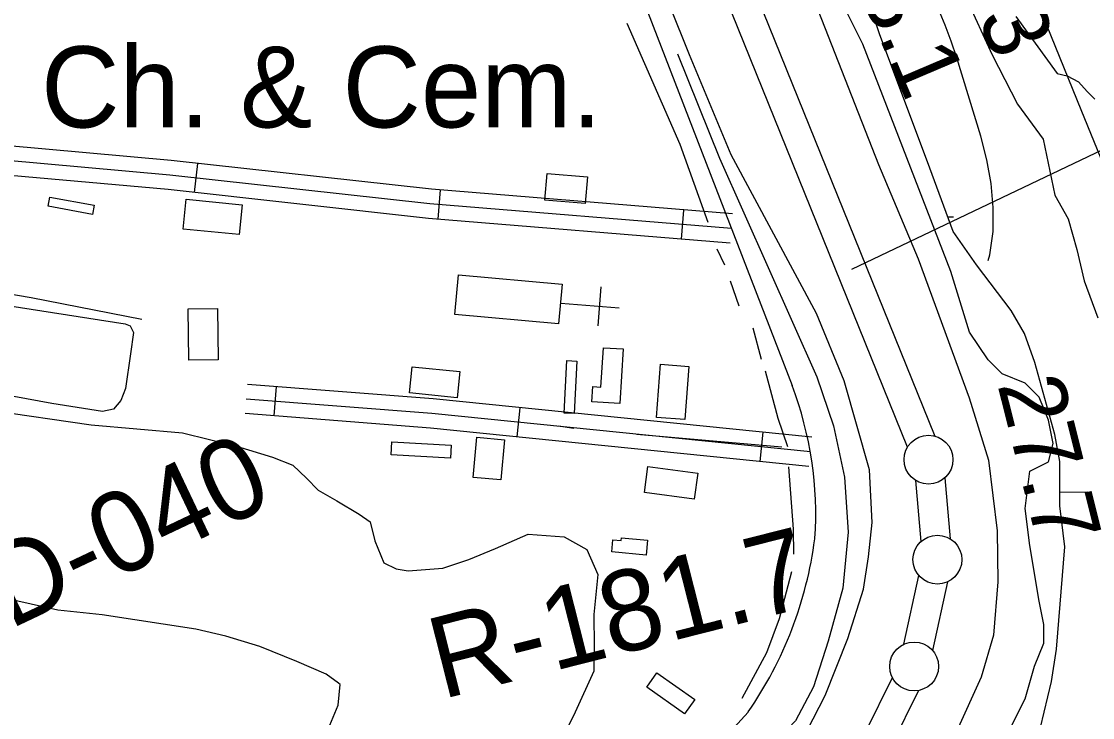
# Model space of a CAD drawing. Extents: x 3355724 to 3393621, y 594744 to 620174.
# Drawn here: x 3383371 to 3384466, y 602796 to 603509 of the extents above; entities that cross this region are included whole.
import ezdxf

# ---------------------------------------------------------------- set-up
doc = ezdxf.new("R2010")
doc.units = 0
for name, color, linetype in [('V-BLDG-OTLN', 7, 'Continuous'), ('V-DTCH-CNTR', 7, 'Continuous'), ('V-LEVE-TOET', 7, 'Continuous'), ('V-RIVR-EDGE', 7, 'Continuous'), ('V-RIVR-RANG', 7, 'Continuous'), ('V-RIVR-RANG-IDEN', 7, 'Continuous'), ('V-ROAD-CNTR', 7, 'Continuous'), ('V-SITE-OTLN', 7, 'Continuous'), ('V-SITE-OTLN-IDEN', 7, 'Continuous'), ('V-SITE-VEGE', 7, 'Continuous'), ('V-SURV-LINE', 7, 'Continuous'), ('V-TOPO-MAJR', 7, 'Continuous'), ('V-TOPO-SHOR', 7, 'Continuous'), ('V-WETL-SWMP', 7, 'Continuous')]:
    doc.layers.add(name, color=color, linetype=linetype)

msp = doc.modelspace()

# ---------------------------------------------------------------- linework, layer by layer
at = {"layer": 'V-BLDG-OTLN'}
for points in [[(3383908.5, 603353.1), (3383949.7, 603349.5), (3383947.3, 603322.2), (3383906.1, 603325.8)], [(3383399.5, 603328.9), (3383445, 603320.4), (3383443.2, 603311), (3383397.8, 603319.5)], [(3383539.1, 603326.6), (3383596.4, 603321), (3383593.4, 603290.5), (3383536.1, 603296)], [(3383817.8, 603249.4), (3383923.9, 603239.6), (3383920.2, 603199.1), (3383814, 603208.8)], [(3383571.3, 603214.7), (3383572, 603162.4), (3383542, 603162), (3383541.3, 603214.3)], [(3383986.2, 603173.5), (3383982.8, 603117.6), (3383954.3, 603119.4), (3383955.3, 603134.8), (3383963.5, 603134.3), (3383966, 603174.7)], [(3383770.2, 603155.2), (3383819.1, 603150.3), (3383816.4, 603123.5), (3383767.5, 603128.4)], [(3383938.9, 603161), (3383936.2, 603107.2), (3383925.8, 603107.8), (3383928.5, 603161.5)], [(3384053.4, 603155.6), (3384049.3, 603101.1), (3384020.4, 603103.3), (3384024.5, 603157.8)], [(3383749.6, 603078.2), (3383810.3, 603074.9), (3383809.6, 603061.7), (3383748.9, 603065)], [(3383864.7, 603080.5), (3383861.1, 603039.3), (3383832.9, 603041.8), (3383836.5, 603083)], [(3384011.6, 603053.1), (3384062.6, 603046.2), (3384058.9, 603019.6), (3384007.9, 603026.6)], [(3383984.6, 602980.2), (3384011.2, 602977.8), (3384009.8, 602962.5), (3383974.6, 602965.7), (3383975.7, 602978), (3383984.3, 602977.2)], [(3384020.7, 602841.9), (3384059.4, 602814.5), (3384049.1, 602799.9), (3384010.4, 602827.3)]]:
    msp.add_lwpolyline(points, close=True, dxfattribs=at)
at = {"layer": 'V-DTCH-CNTR'}
msp.add_lwpolyline([(3383342.9, 603219.8), (3383476.8, 603199.2), (3383481.7, 603197.2), (3383481.7, 603197.2), (3383485.3, 603190.3), (3383482.1, 603168.5), (3383477, 603132.8), (3383472.3, 603120.8), (3383464.7, 603111.6), (3383453.5, 603109.3), (3383401.6, 603117.7), (3383336.4, 603129.5)], dxfattribs=at)
at = {"layer": 'V-LEVE-TOET'}
for points in [[(3383511.6, 605084.7), (3383574.3, 604975.1), (3383627.4, 604850.1), (3383694.6, 604700.2), (3383729.7, 604619.8), (3383745.1, 604594.8), (3383764.1, 604575.9), (3383781.9, 604561.4), (3383793.6, 604547.4), (3383799.7, 604528.5), (3383801.7, 604504.7), (3383798.1, 604491.2), (3383797.6, 604463.1), (3383807.5, 604430.8), (3383892.6, 604235.2), (3383960.5, 604073.6), (3384024, 603920.7), (3384108, 603704.2), (3384171.6, 603555.5), (3384247.5, 603362.3)], [(3384096.6, 603372), (3384054.1, 603474.4), (3384014.5, 603573.2), (3383970.1, 603676.2), (3383930.7, 603768.8), (3383902.2, 603842), (3383860.3, 603941.9), (3383827.6, 604026), (3383786.8, 604124.2), (3383748, 604213.2), (3383707.3, 604311.3), (3383669, 604402.1), (3383631.3, 604501.5), (3383574.6, 604638.6), (3383536.3, 604736.8), (3383486.3, 604853.2), (3383452.4, 604928.1), (3383417.9, 604989.7), (3383371.8, 605068.8)], [(3384247.5, 603362.3), (3384288, 603265.6), (3384340.3, 603123.5), (3384360, 603059.4), (3384368.7, 602987.4), (3384369.4, 602934.9), (3384365.2, 602880.3), (3384352.5, 602837.4), (3384327.4, 602781.8), (3384263.6, 602681.6), (3384175.5, 602576.8), (3384091.9, 602494.5), (3383993, 602404.3), (3383883.1, 602305.6), (3383782.8, 602218.1), (3383685.1, 602142.6), (3383599.3, 602070.8), (3383584.9, 602047.5), (3383541.4, 602002.1)], [(3384151.9, 602746.1), (3384168.3, 602770.8), (3384192.9, 602818.7), (3384215.9, 602877.1), (3384232, 602927.7), (3384237.2, 602960.7), (3384240.9, 602995.8), (3384238.1, 603049.6), (3384212.3, 603140.9), (3384184.1, 603209.8), (3384096.6, 603372)]]:
    msp.add_lwpolyline(points, dxfattribs=at)
at = {"layer": 'V-RIVR-EDGE'}
msp.add_spline([(3382685.2, 606951.8), (3382699.4, 606928.4), (3382711.8, 606916.3), (3382716.9, 606906), (3382724.9, 606891.8), (3382727.4, 606883), (3382735.5, 606874.6), (3382743.1, 606862.5), (3382749.7, 606847.8), (3382757.7, 606833.2), (3382769.7, 606814.2), (3382782.1, 606791.1), (3382790, 606772.8), (3382795.5, 606757.4), (3382803.9, 606738.8), (3382815.9, 606716.1), (3382833, 606684.6), (3382843.1, 606660.1), (3382859.5, 606629.7), (3382875.2, 606604.8), (3382892.7, 606579.2), (3382909.8, 606553.2), (3382929.1, 606522.4), (3382946.9, 606497.2), (3382961.9, 606475.9), (3382973.2, 606466.8), (3382978.6, 606458.7), (3382989.2, 606442.6), (3382998.3, 606426.5), (3383008.1, 606410.7), (3383014.7, 606399.4), (3383025.6, 606390.2), (3383035.5, 606378.9), (3383042.4, 606369.7), (3383049.7, 606356.5), (3383077.3, 606319.5), (3383102.5, 606284), (3383117.1, 606263.2), (3383116.7, 606258), (3383121.8, 606250.7), (3383131.6, 606239), (3383143.6, 606222.1), (3383154.2, 606202.7), (3383171.3, 606174.9), (3383191.3, 606140.5), (3383212.1, 606099.5), (3383234.2, 606053), (3383253.5, 606015), (3383268.8, 605988.3), (3383282.6, 605965.6), (3383296.1, 605942.5), (3383311, 605917.6), (3383331.4, 605885.4), (3383347.5, 605861.2), (3383359.5, 605840), (3383382.8, 605801.5), (3383403.9, 605764.9), (3383419.5, 605733.8), (3383436.6, 605710.8), (3383464.3, 605675.6), (3383488.4, 605644.5), (3383503.7, 605625), (3383518.6, 605606.4), (3383529.6, 605590.3), (3383543.8, 605575.6), (3383545.2, 605570.8), (3383546.7, 605564.6), (3383550.3, 605557.3), (3383562, 605549.6), (3383575.1, 605539.3), (3383595.9, 605513.7), (3383606.8, 605500.9), (3383607.9, 605493.9), (3383610.4, 605479.7), (3383611.9, 605471.2), (3383617, 605461), (3383626.1, 605438.7), (3383628.9, 605416.4), (3383634.4, 605397), (3383636.2, 605387.5), (3383638, 605374.3), (3383643, 605364.1), (3383654.3, 605347.6), (3383664.2, 605328.6), (3383678.7, 605296), (3383684.5, 605268.6), (3383701.5, 605220.3), (3383711.7, 605194.6), (3383715, 605180), (3383724, 605149.3), (3383729.8, 605134.3), (3383736, 605118.6), (3383753.8, 605084.9), (3383770.6, 605064.7), (3383787.4, 605049), (3383790.6, 605036.5), (3383801.2, 605013.1), (3383814.6, 604980.5), (3383827.4, 604948.7), (3383833.5, 604933), (3383843.7, 604917.2), (3383863, 604890.5), (3383884.5, 604857.2), (3383935.1, 604783.6), (3383963.9, 604731.6), (3383993.7, 604668.7), (3384001, 604651.5), (3384017.4, 604619.6), (3384033, 604587), (3384044.7, 604571.3), (3384055.6, 604554.1), (3384071.6, 604521.1), (3384078.5, 604500.3), (3384081.7, 604484.6), (3384087.9, 604472.1), (3384096.7, 604460.8), (3384103.2, 604452.3), (3384105.4, 604442.5), (3384107.2, 604435.9), (3384108.7, 604434.4), (3384114.9, 604433.7), (3384119.6, 604430.7), (3384126.5, 604421.9), (3384146.9, 604390.5), (3384166.9, 604355.7), (3384183.3, 604328.2), (3384207, 604298.9), (3384223.4, 604274), (3384250.3, 604225.3), (3384274, 604180), (3384294, 604141.5), (3384308.5, 604112.6), (3384320.9, 604089.5), (3384332.2, 604075.6), (3384335.8, 604069), (3384345.3, 604053.3), (3384349, 604047.8), (3384362.1, 604035), (3384372.3, 604022.9), (3384383.9, 604005.7), (3384390.1, 603992.9), (3384406.2, 603972.4), (3384417.1, 603955.2), (3384430.6, 603933.9), (3384440.8, 603916.7), (3384450.2, 603895.9), (3384454.2, 603879), (3384458.5, 603863.7), (3384464.3, 603844.6), (3384471.6, 603825.2), (3384474.9, 603815), (3384473.7, 603806.6), (3384477.7, 603791.2), (3384479.2, 603782.1), (3384477.7, 603771.1), (3384476.2, 603762), (3384476.2, 603748.8), (3384482, 603727.6), (3384486.7, 603712.3), (3384487, 603701.3), (3384487, 603678.6), (3384496.3, 603630), (3384507.6, 603590.8), (3384519.5, 603555.7), (3384533.4, 603523.5), (3384552.6, 603483.6), (3384569, 603455.8), (3384585.8, 603432.7), (3384604.3, 603404.5), (3384620.7, 603379.6), (3384633.8, 603347.1), (3384649.1, 603299.9), (3384654.8, 603268.1), (3384673.3, 603196.4), (3384684.5, 603140.8), (3384695.3, 603099.8), (3384709.2, 603067.6), (3384721.9, 603042.4), (3384733.5, 603015.6), (3384746.6, 602984.9), (3384755, 602962.2), (3384756.8, 602956), (3384760.4, 602956), (3384764.4, 602951.2), (3384767.7, 602926.7), (3384780.3, 602867.1), (3384791.2, 602833.8), (3384810.8, 602780.4), (3384833, 602721.9), (3384845.3, 602691.5), (3384855.1, 602674.7), (3384859.5, 602657.8), (3384867.5, 602641.7), (3384876.9, 602624.5), (3384884.6, 602600.7), (3384894, 602572.2), (3384900.5, 602547), (3384906.7, 602528.3), (3384922.7, 602491.3), (3384928.8, 602472.3), (3384931.7, 602454), (3384931.3, 602436.9), (3384923.2, 602425.2), (3384917, 602416.1), (3384910.8, 602406.9), (3384908.2, 602392.3), (3384903, 602383.2), (3384897.5, 602375.9), (3384886.5, 602362), (3384870.4, 602324.1), (3384866.3, 602310.9), (3384859.7, 602289.4), (3384857.5, 602280.2), (3384853.4, 602271.8), (3384850.1, 602256.5), (3384849.3, 602232), (3384850.7, 602216.6), (3384853.2, 602202.4), (3384853.6, 602202.4), (3384862, 602201.2), (3384874.1, 602196.5), (3384877.3, 602195.4), (3384877.3, 602192.4), (3384871.5, 602184), (3384871.1, 602180.4), (3384872.9, 602176.7), (3384876.2, 602170.9), (3384874.7, 602165), (3384869.6, 602153.7), (3384865.5, 602149.3), (3384863, 602143.1), (3384862.9, 602137.6), (3384862.9, 602133.3), (3384868, 602129.6), (3384875.7, 602123), (3384879, 602114.9), (3384881.9, 602107.3), (3384887, 602100.7), (3384894.3, 602097), (3384896.5, 602092.2), (3384897.2, 602079.4), (3384899.7, 602068.1), (3384904.8, 602054.9), (3384914.2, 602039.5), (3384933.2, 602016.8), (3384944.9, 601998.2), (3384955.4, 601973.3), (3384961.9, 601937.8), (3384969.5, 601902), (3384976.3, 601868.7), (3384986.5, 601837.6), (3384990.8, 601821.5), (3384996.2, 601784.6), (3385007.4, 601717.3), (3385010.6, 601690.6), (3385019.6, 601642.3), (3385024.3, 601622.9), (3385033.4, 601587.1), (3385047.9, 601537.3), (3385059.8, 601482.8), (3385064.1, 601458.7), (3385063.7, 601433.8), (3385064.8, 601415.9), (3385066.9, 601389.2), (3385067.9, 601365.1), (3385069, 601353.4), (3385072.6, 601339.9), (3385083.5, 601316.8), (3385087.9, 601310.6), (3385095.6, 601305.1), (3385098.1, 601299.6), (3385101.8, 601293.7), (3385102.5, 601289), (3385102.5, 601285.7), (3385105.8, 601284.6), (3385109.8, 601282.4), (3385109.8, 601280.9), (3385112.7, 601280.5), (3385119.6, 601280.5), (3385121.8, 601278.3), (3385122.2, 601265.2), (3385118.1, 601257.1), (3385117.7, 601251.3), (3385118.1, 601238.1), (3385119.8, 601205.6), (3385118, 601200.8), (3385117.6, 601193.9), (3385120.9, 601189.1), (3385123.1, 601189.1), (3385128.5, 601189.1), (3385132.2, 601189.1), (3385142.8, 601181.8), (3385149, 601173), (3385150.8, 601159.5), (3385150.4, 601141.5), (3385148.5, 601137.5), (3385144.9, 601132.8), (3385144.1, 601125.8), (3385146.3, 601120), (3385150.3, 601115.6), (3385159.8, 601111.2), (3385160.1, 601107.2), (3385154.7, 601103.9), (3385152.8, 601099.1), (3385152.8, 601092.9), (3385153.5, 601084.9), (3385156.8, 601080.1), (3385159.3, 601079.4), (3385173.2, 601082.3), (3385173.2, 601080.8), (3385172.8, 601061.4), (3385176.1, 601037.7), (3385179, 601025.6), (3385187, 601006.9), (3385193.5, 600994.8), (3385203, 600979.8), (3385216.5, 600962.3), (3385223.7, 600948), (3385225.9, 600931.2), (3385225.8, 600905.6), (3385225.4, 600892), (3385233.1, 600875.6), (3385237.4, 600855.5), (3385241.3, 600826.6), (3385242.4, 600796.6), (3385245.5, 600741.4), (3385245.8, 600708.9), (3385249.6, 600639.4), (3385250.3, 600596.6), (3385259.6, 600509.6), (3385266.4, 600451.1), (3385277.5, 600369.2), (3385281.8, 600323.5), (3385282.7, 600271.6), (3385283.4, 600237.2), (3385284.3, 600195.1)], degree=3, dxfattribs=at)
at = {"layer": 'V-RIVR-RANG'}
msp.add_line((3384220, 603255.1), (3385050.3, 603651.4), dxfattribs=at)
at = {"layer": 'V-ROAD-CNTR'}
for p, q in [((3383547.8, 603333.5), (3383551.1, 603363.3)), ((3383796.8, 603306.2), (3383799.2, 603336.1)), ((3384045.9, 603285.7), (3384048.4, 603315.6)), ((3383629, 603104.9), (3383631.4, 603134.8)), ((3383877.7, 603083.4), (3383880.7, 603113.2)), ((3384126.5, 603058.2), (3384129.5, 603088.1))]:
    msp.add_line(p, q, dxfattribs=at)
for points in [[(3382114.2, 606889.5), (3382318.1, 606591.4), (3382554.9, 606233.6), (3382633.5, 606115.6), (3382780.5, 605897.5), (3382958.4, 605622.5), (3383146.4, 605341.9), (3383279.8, 605147.1), (3383351.2, 605037.9), (3383418.1, 604924.1), (3383451.1, 604860.5), (3383485.5, 604784.6), (3383628.2, 604432.8), (3383792.7, 604038.1), (3383916.7, 603743.2), (3383965, 603638.1), (3384159, 603136)], [(3384098.2, 603311.6), (3383790, 603336.9), (3383523.8, 603366.4), (3383307.9, 603385.6), (3383070.5, 603410)], [(3384097, 603296.6), (3383788.5, 603321.9), (3383522.3, 603351.4), (3383306.5, 603370.7), (3383069, 603395.1)], [(3384095.7, 603281.7), (3383787.1, 603307), (3383520.8, 603336.5), (3383305, 603355.8), (3383067.5, 603380.2)], [(3384179.2, 603083.1), (3383791.7, 603122.2), (3383601.8, 603137.1)], [(3384177.7, 603068.1), (3383790.3, 603107.3), (3383600.6, 603122.1)], [(3384176.2, 603053.2), (3383789, 603092.3), (3383599.4, 603107.2)], [(3384114.1, 602801.8), (3383952.3, 602624.5), (3383735.4, 602405.1), (3383594.6, 602283.8), (3383229.2, 601986.7), (3383078.6, 601871.4), (3383013.6, 601825.4), (3382898.3, 601744.6), (3382671.4, 601604.9), (3382435.6, 601459.3), (3382349.1, 601405.5), (3382248.5, 601337.8)]]:
    msp.add_lwpolyline(points, dxfattribs=at)
for centre, radius, start, end in [((3383814.4, 603004.6), 368.8, 356.0617, 20.8662), ((3383784.7, 603030.2), 400.8, 325.2664, 352.6581)]:
    msp.add_arc(centre, radius, start, end, dxfattribs=at)
at = {"layer": 'V-SITE-OTLN'}
for p, q in [((3383960.6, 603197), (3383963.7, 603236.9)), ((3383922.3, 603220.1), (3383982.1, 603215.4))]:
    msp.add_line(p, q, dxfattribs=at)
at = {"layer": 'V-SITE-VEGE'}
for p, q in [((3384231.3, 603485.3), (3384212.3, 603523.4)), ((3384388, 603513.8), (3384430.2, 603455.3)), ((3384321.5, 603252.5), (3384231.3, 603485.3)), ((3384430.2, 603455.3), (3384440.4, 603453)), ((3384440.4, 603453), (3384452.2, 603446.9)), ((3384452.2, 603446.9), (3384460.9, 603436.9)), ((3384460.9, 603436.9), (3384468.9, 603429.1)), ((3384340.5, 603190.7), (3384321.5, 603252.5)), ((3384359.5, 603162.2), (3384340.5, 603190.7)), ((3384373.8, 603148), (3384359.5, 603162.2)), ((3384397.5, 603138.5), (3384373.8, 603148)), ((3384411.8, 603124.2), (3384397.5, 603138.5)), ((3384421.3, 603100.5), (3384411.8, 603124.2)), ((3384426, 603076.7), (3384421.3, 603100.5)), ((3384421.3, 603057.7), (3384426, 603076.7)), ((3384402.3, 603048.2), (3384421.3, 603057.7)), ((3384397.5, 603010.2), (3384402.3, 603048.2)), ((3384402.3, 602972.2), (3384397.5, 603010.2)), ((3384411.8, 602915.1), (3384402.3, 602972.2)), ((3384416.5, 602891.4), (3384411.8, 602915.1)), ((3384416.5, 602872.4), (3384416.5, 602891.4)), ((3384407, 602848.6), (3384416.5, 602872.4)), ((3384397.5, 602815.4), (3384407, 602848.6)), ((3384383.3, 602786.9), (3384397.5, 602815.4))]:
    msp.add_line(p, q, dxfattribs=at)
for points in [[(3383338.2, 603110.6), (3383442, 603095.6), (3383535.5, 603087.4), (3383590.6, 603074), (3383627.6, 603062.8), (3383648.1, 603054.4), (3383662.4, 603041.3), (3383674.3, 603028.9), (3383693.3, 603018.1), (3383716.2, 603004.3), (3383727.3, 602996.6), (3383732.3, 602977.1), (3383741.2, 602954.4), (3383753.9, 602948.3), (3383766.4, 602946.2), (3383801.7, 602949), (3383828.3, 602958), (3383855.6, 602969.3), (3383889.1, 602983.9), (3383926, 602981.2), (3383948.9, 602968.2), (3383960.3, 602942.5), (3383956.1, 602901.6), (3383956.5, 602868.7), (3383956.1, 602843.6), (3383937.1, 602801.7), (3383924.1, 602774.9)], [(3383686.2, 602788.2), (3383694.5, 602808.7), (3383696.6, 602829.9), (3383695, 602831.4), (3383682.3, 602840.7), (3383652.3, 602853.6), (3383614.5, 602868.8), (3383579.8, 602879.3), (3383549.1, 602886.7), (3383453.2, 602901.1), (3383407.7, 602906), (3383325.8, 602924.5)]]:
    msp.add_lwpolyline(points, dxfattribs=at)
at = {"layer": 'V-SURV-LINE'}
for points in [[(3383556.3, 604935.8), (3384305.1, 603084.3)], [(3384277.2, 603073), (3383528.5, 604924.6)], [(3384291, 602976.4), (3384285.5, 603038.9)], [(3384315.4, 603041.6), (3384320.9, 602979)], [(3384273.5, 602871.1), (3384288.8, 602941.5)], [(3384318.1, 602935.1), (3384302.8, 602864.7)], [(3384234, 602781.3), (3384261.6, 602837.1)], [(3384288.5, 602823.8), (3384260.9, 602768)]]:
    msp.add_lwpolyline(points, dxfattribs=at)
for centre in [(3384298.6, 603060.1), (3384307.7, 602957.8), (3384283.9, 602848.4)]:
    msp.add_circle(centre, 25, dxfattribs=at)
at = {"layer": 'V-TOPO-MAJR'}
for points in [[(3384359.8, 603263.9), (3384361.4, 603269.6), (3384364.8, 603293.5), (3384364.6, 603318.3), (3384362.6, 603342.9), (3384358.2, 603367.1), (3384352.2, 603391.1), (3384327.5, 603471.5), (3384321.9, 603488.3), (3384315.8, 603504.8), (3384308.9, 603521.1), (3384301.5, 603537.1), (3384107.3, 603932.3), (3384094.8, 603957.5), (3384082.3, 603982.6), (3384069.7, 604007.8), (3384057, 604032.8), (3384037, 604072.3), (3384034.2, 604077.6), (3384031.3, 604082.8), (3384028.2, 604088), (3384025.1, 604093.1), (3384019.2, 604102.3), (3384012.8, 604108.3)], [(3384415.1, 603514.9), (3384454.4, 603418.4), (3384478, 603360.7)]]:
    msp.add_lwpolyline(points, dxfattribs=at)
at = {"layer": 'V-TOPO-SHOR'}
for p, q in [((3384081.9, 603275.9), (3384089.9, 603259.6)), ((3384095.6, 603243.2), (3384104.6, 603217.4)), ((3384119, 603194.9), (3384127.3, 603162.8)), ((3384131.4, 603151.1), (3384144.6, 603102.6)), ((3384144.6, 603102.6), (3384154.4, 603073.7)), ((3383935.7, 603092.1), (3383920, 603094.3)), ((3384148.5, 603073), (3384000.1, 603085.9))]:
    msp.add_line(p, q, dxfattribs=at)
for points in [[(3383990.1, 603506.9), (3384044.3, 603382.9), (3384072.9, 603303.3)], [(3384041.9, 603475.4), (3384084.9, 603368.5), (3384184.4, 603144.7), (3384201.5, 603094.7), (3384212.5, 603042.3), (3384216.3, 602985.8), (3384210.8, 602928.5), (3384195.9, 602874.2), (3384180.8, 602827.7), (3384162.5, 602792.9), (3384131.5, 602760.3), (3384084.3, 602708.7), (3384043.3, 602668.9), (3383948.9, 602572.7), (3383879.1, 602509.8), (3383725.8, 602358.7), (3383597.9, 602244), (3383444.3, 602116.4), (3383199, 601920.1)], [(3383493.9, 603203.7), (3383380.6, 603225.8), (3383260.3, 603246.1), (3383227.2, 603255.1), (3383194.1, 603266.4), (3383146, 603283.8), (3383127.1, 603289), (3383045.4, 603302.1), (3382948.7, 603318), (3382925.9, 603320.1), (3382852.1, 603324.6), (3382816.7, 603329.6), (3382735.8, 603338.7), (3382632.1, 603349.1)], [(3384155.5, 603052.6), (3384160.2, 602989.1), (3384160.6, 602963.2)], [(3384158.5, 602945.2), (3384145.8, 602897.1), (3384132.9, 602862.4), (3384107.7, 602815.8)]]:
    msp.add_lwpolyline(points, dxfattribs=at)
at = {"layer": 'V-WETL-SWMP'}
for p, q in [((3384248.8, 603494.8), (3384215.4, 603594.8)), ((3384334.7, 603537.9), (3384363.6, 603474.5)), ((3384297.6, 603365), (3384248.8, 603494.8)), ((3384363.6, 603474.5), (3384389.5, 603424)), ((3384389.5, 603424), (3384415.9, 603388.1)), ((3384415.9, 603388.1), (3384427.8, 603330.7)), ((3384323.7, 603293.7), (3384297.6, 603365)), ((3384427.8, 603330.7), (3384441.5, 603306.5)), ((3384318.3, 603308.5), (3384324.1, 603308.6)), ((3384441.5, 603306.5), (3384450.5, 603275.1)), ((3384347.8, 603259.4), (3384323.7, 603293.7)), ((3384450.5, 603275.1), (3384458, 603243)), ((3384383, 603212.7), (3384347.8, 603259.4)), ((3384458, 603243), (3384471.9, 603205.4)), ((3384396.7, 603189.2), (3384383, 603212.7)), ((3384407.3, 603159.5), (3384396.7, 603189.2)), ((3384428, 603085.8), (3384407.3, 603159.5)), ((3384433.1, 603058.3), (3384428, 603085.8)), ((3384432.9, 603012.7), (3384433.1, 603058.3)), ((3384433, 603026.9), (3384461.5, 603027)), ((3384438.2, 602971), (3384432.9, 603012.7)), ((3384429.4, 602866.2), (3384438.2, 602971)), ((3384424.3, 602833.1), (3384429.4, 602866.2)), ((3384413.1, 602785.8), (3384424.3, 602833.1))]:
    msp.add_line(p, q, dxfattribs=at)

# ---------------------------------------------------------------- texts
at = {"layer": 'V-RIVR-RANG'}
for s, rotation, p in [('28.3', 293.0583, (3384299.2, 603626.9)), ('23.1', 293.0583, (3384208.2, 603585.3)), ('27.7', 284.0883, (3384369, 603137))]:
    msp.add_text(s, height=67, rotation=rotation, dxfattribs=at).set_placement(p)
at = {"layer": 'V-RIVR-RANG-IDEN'}
for s, rotation, p in [('D-040', 25.3753, (3383358.3, 602885.9)), ('R-181.7', 14.2269, (3383800.8, 602814.7))]:
    msp.add_text(s, height=83, rotation=rotation, dxfattribs=at).set_placement(p)
at = {"layer": 'V-SITE-OTLN-IDEN'}
msp.add_text('Ch. & Cem.', height=83, dxfattribs=at).set_placement((3383390.7, 603400.1))

doc.saveas('drawing.dxf')
